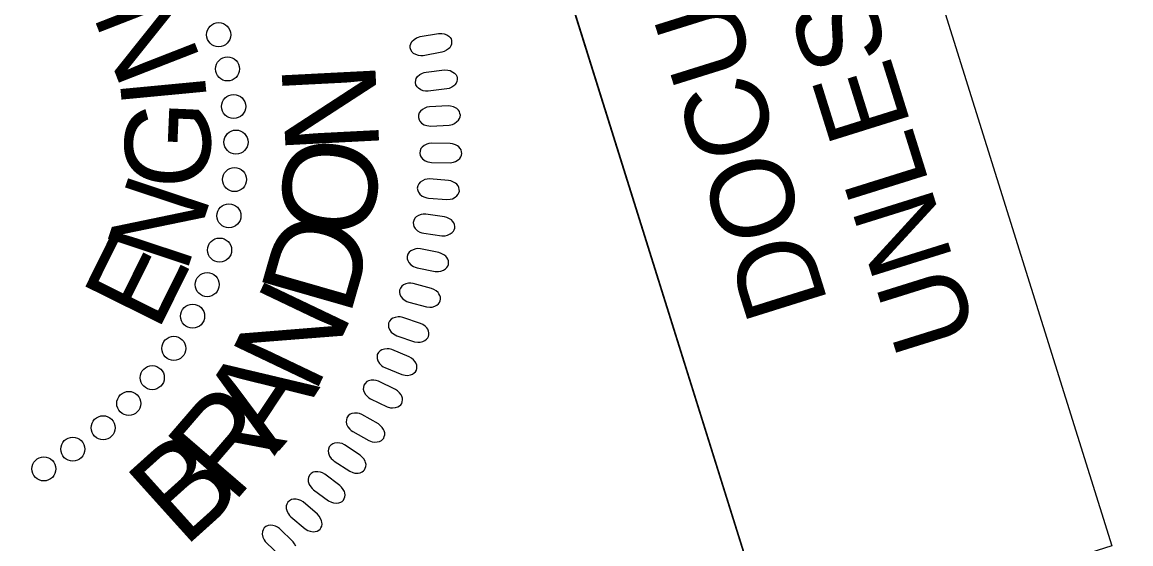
# Model space of a CAD drawing. Extents: x 473667 to 478950, y 494687 to 505998.
# Drawn here: x 473846.6 to 473920.4, y 505522 to 505556.7 of the extents above; entities that cross this region are included whole.
import ezdxf

# ---------------------------------------------------------------- set-up
doc = ezdxf.new("R2010")
doc.units = 0
for name, color, linetype in [('Sheet Layout Plan Border', 7, 'Continuous'), ('Sheet PE Seal Cell', 7, 'Continuous'), ('Sheet Plan CELL', 7, 'Continuous'), ('Sheet Sticker Exception Certification CELL', 7, 'Continuous')]:
    doc.layers.add(name, color=color, linetype=linetype)

msp = doc.modelspace()

# ---------------------------------------------------------------- linework, layer by layer
at = {"layer": 'Sheet Layout Plan Border'}
msp.add_lwpolyline([(474406.845, 504597.013), (474903.647, 504485.248), (475129.181, 504591.075), (474710.642, 505927.062), (474746.684, 505812.014), (474670.328, 505788.092), (474619.338, 505950.854), (473859.326, 505712.757), (473919.128, 505521.868), (473753.519, 505469.973), (474127.2, 504277.174)], close=True, dxfattribs=at)
at = {"layer": 'Sheet PE Seal Cell'}
for points in [[(473873.109, 505555.763), (473874.316, 505555.979), (473874.538, 505555.981), (473874.686, 505555.955), (473874.872, 505555.874), (473874.997, 505555.798), (473875.096, 505555.702), (473875.153, 505555.606), (473875.193, 505555.499), (473875.193, 505555.385), (473875.185, 505555.262), (473875.145, 505555.148), (473875.064, 505555.028), (473874.996, 505554.955), (473874.861, 505554.862), (473874.695, 505554.772), (473874.542, 505554.721), (473873.307, 505554.492), (473873.136, 505554.484), (473872.99, 505554.504), (473872.818, 505554.564), (473872.66, 505554.649), (473872.565, 505554.731), (473872.478, 505554.875), (473872.432, 505555.019), (473872.445, 505555.173), (473872.475, 505555.285), (473872.551, 505555.428), (473872.697, 505555.574), (473872.862, 505555.673), (473872.984, 505555.725)], [(473873.505, 505553.407), (473874.724, 505553.548), (473874.946, 505553.536), (473875.091, 505553.5), (473875.272, 505553.408), (473875.392, 505553.324), (473875.484, 505553.222), (473875.536, 505553.122), (473875.568, 505553.013), (473875.561, 505552.9), (473875.545, 505552.777), (473875.498, 505552.667), (473875.411, 505552.551), (473875.338, 505552.483), (473875.197, 505552.399), (473875.026, 505552.319), (473874.87, 505552.278), (473873.623, 505552.127), (473873.451, 505552.13), (473873.308, 505552.159), (473873.139, 505552.229), (473872.987, 505552.324), (473872.897, 505552.412), (473872.82, 505552.561), (473872.783, 505552.708), (473872.806, 505552.86), (473872.843, 505552.97), (473872.927, 505553.108), (473873.082, 505553.245), (473873.253, 505553.333), (473873.377, 505553.377)], [(473873.806, 505549.811), (473875.031, 505549.875), (473875.248, 505549.923), (473875.385, 505549.982), (473875.549, 505550.104), (473875.653, 505550.206), (473875.727, 505550.323), (473875.762, 505550.429), (473875.776, 505550.542), (473875.749, 505550.653), (473875.713, 505550.771), (473875.649, 505550.872), (473875.543, 505550.971), (473875.461, 505551.027), (473875.308, 505551.086), (473875.125, 505551.137), (473874.965, 505551.151), (473873.71, 505551.094), (473873.542, 505551.062), (473873.404, 505551.01), (473873.25, 505550.912), (473873.116, 505550.793), (473873.042, 505550.692), (473872.99, 505550.531), (473872.978, 505550.382), (473873.025, 505550.234), (473873.081, 505550.132), (473873.187, 505550.01), (473873.362, 505549.9), (473873.545, 505549.842), (473873.676, 505549.819)], [(473873.861, 505547.384), (473875.088, 505547.37), (473875.308, 505547.405), (473875.448, 505547.456), (473875.619, 505547.566), (473875.73, 505547.662), (473875.811, 505547.774), (473875.851, 505547.877), (473875.873, 505547.99), (473875.854, 505548.102), (473875.825, 505548.222), (473875.767, 505548.327), (473875.668, 505548.433), (473875.589, 505548.494), (473875.44, 505548.562), (473875.261, 505548.624), (473875.102, 505548.649), (473873.846, 505548.67), (473873.675, 505548.649), (473873.536, 505548.605), (473873.375, 505548.517), (473873.234, 505548.407), (473873.153, 505548.31), (473873.092, 505548.155), (473873.07, 505548.005), (473873.109, 505547.855), (473873.158, 505547.75), (473873.255, 505547.622), (473873.424, 505547.501), (473873.603, 505547.431), (473873.732, 505547.4)], [(473873.661, 505545.006), (473874.884, 505544.916), (473875.106, 505544.937), (473875.249, 505544.978), (473875.427, 505545.078), (473875.543, 505545.167), (473875.631, 505545.273), (473875.678, 505545.374), (473875.707, 505545.485), (473875.695, 505545.598), (473875.674, 505545.72), (473875.622, 505545.828), (473875.53, 505545.94), (473875.455, 505546.005), (473875.311, 505546.083), (473875.136, 505546.156), (473874.979, 505546.191), (473873.726, 505546.291), (473873.555, 505546.281), (473873.413, 505546.246), (473873.247, 505546.169), (473873.099, 505546.067), (473873.013, 505545.976), (473872.941, 505545.824), (473872.91, 505545.676), (473872.94, 505545.524), (473872.982, 505545.416), (473873.071, 505545.282), (473873.232, 505545.15), (473873.406, 505545.07), (473873.533, 505545.031)], [(473873.335, 505542.675), (473874.55, 505542.508), (473874.772, 505542.515), (473874.918, 505542.547), (473875.101, 505542.636), (473875.223, 505542.717), (473875.317, 505542.817), (473875.371, 505542.915), (473875.406, 505543.024), (473875.401, 505543.137), (473875.388, 505543.26), (473875.343, 505543.372), (473875.258, 505543.489), (473875.188, 505543.56), (473875.049, 505543.646), (473874.879, 505543.73), (473874.724, 505543.774), (473873.48, 505543.953), (473873.309, 505543.953), (473873.165, 505543.927), (473872.994, 505543.861), (473872.841, 505543.769), (473872.748, 505543.683), (473872.668, 505543.536), (473872.628, 505543.39), (473872.647, 505543.237), (473872.682, 505543.126), (473872.763, 505542.987), (473872.915, 505542.846), (473873.084, 505542.754), (473873.208, 505542.707)], [(473872.895, 505540.378), (473874.097, 505540.136), (473874.319, 505540.129), (473874.467, 505540.152), (473874.655, 505540.229), (473874.782, 505540.302), (473874.882, 505540.396), (473874.942, 505540.491), (473874.984, 505540.597), (473874.986, 505540.71), (473874.981, 505540.834), (473874.943, 505540.948), (473874.866, 505541.07), (473874.8, 505541.145), (473874.666, 505541.241), (473874.502, 505541.335), (473874.35, 505541.389), (473873.12, 505541.644), (473872.95, 505541.656), (473872.803, 505541.639), (473872.629, 505541.583), (473872.47, 505541.502), (473872.373, 505541.422), (473872.283, 505541.28), (473872.234, 505541.137), (473872.244, 505540.983), (473872.272, 505540.87), (473872.344, 505540.726), (473872.487, 505540.576), (473872.649, 505540.473), (473872.77, 505540.419)], [(473872.338, 505538.09), (473873.523, 505537.772), (473873.744, 505537.751), (473873.893, 505537.765), (473874.086, 505537.829), (473874.216, 505537.895), (473874.322, 505537.982), (473874.389, 505538.073), (473874.436, 505538.176), (473874.447, 505538.289), (473874.449, 505538.413), (473874.418, 505538.529), (473874.349, 505538.656), (473874.287, 505538.735), (473874.161, 505538.839), (473874.003, 505538.943), (473873.854, 505539.006), (473872.643, 505539.339), (473872.473, 505539.361), (473872.327, 505539.354), (473872.149, 505539.309), (473871.985, 505539.237), (473871.883, 505539.163), (473871.784, 505539.028), (473871.727, 505538.888), (473871.727, 505538.733), (473871.747, 505538.619), (473871.81, 505538.471), (473871.943, 505538.312), (473872.1, 505538.2), (473872.217, 505538.137)], [(473871.558, 505535.852), (473872.721, 505535.461), (473872.94, 505535.426), (473873.089, 505535.431), (473873.286, 505535.483), (473873.421, 505535.54), (473873.532, 505535.621), (473873.604, 505535.707), (473873.658, 505535.807), (473873.675, 505535.92), (473873.685, 505536.043), (473873.662, 505536.161), (473873.6, 505536.292), (473873.545, 505536.374), (473873.423, 505536.486), (473873.273, 505536.6), (473873.129, 505536.672), (473871.941, 505537.08), (473871.773, 505537.113), (473871.626, 505537.115), (473871.446, 505537.081), (473871.278, 505537.02), (473871.172, 505536.953), (473871.064, 505536.824), (473870.997, 505536.688), (473870.988, 505536.533), (473871.002, 505536.418), (473871.055, 505536.266), (473871.178, 505536.099), (473871.327, 505535.978), (473871.44, 505535.908)], [(473870.754, 505533.734), (473871.89, 505533.27), (473872.107, 505533.222), (473872.256, 505533.217), (473872.455, 505533.257), (473872.594, 505533.306), (473872.71, 505533.379), (473872.787, 505533.461), (473872.848, 505533.557), (473872.871, 505533.668), (473872.888, 505533.79), (473872.873, 505533.909), (473872.819, 505534.045), (473872.769, 505534.13), (473872.656, 505534.249), (473872.513, 505534.372), (473872.373, 505534.453), (473871.212, 505534.935), (473871.047, 505534.979), (473870.9, 505534.989), (473870.719, 505534.967), (473870.548, 505534.917), (473870.436, 505534.857), (473870.322, 505534.734), (473870.247, 505534.603), (473870.228, 505534.45), (473870.235, 505534.333), (473870.279, 505534.178), (473870.39, 505534.004), (473870.531, 505533.873), (473870.64, 505533.797)], [(473869.799, 505531.664), (473870.903, 505531.13), (473871.117, 505531.068), (473871.265, 505531.054), (473871.467, 505531.081), (473871.609, 505531.121), (473871.729, 505531.187), (473871.81, 505531.263), (473871.877, 505531.356), (473871.907, 505531.465), (473871.932, 505531.586), (473871.925, 505531.706), (473871.88, 505531.844), (473871.835, 505531.932), (473871.729, 505532.059), (473871.594, 505532.19), (473871.46, 505532.28), (473870.332, 505532.834), (473870.17, 505532.888), (473870.024, 505532.908), (473869.842, 505532.897), (473869.668, 505532.857), (473869.553, 505532.804), (473869.431, 505532.689), (473869.347, 505532.563), (473869.319, 505532.411), (473869.318, 505532.295), (473869.352, 505532.137), (473869.453, 505531.956), (473869.585, 505531.817), (473869.689, 505531.734)], [(473868.621, 505529.476), (473869.689, 505528.874), (473869.898, 505528.798), (473870.046, 505528.775), (473870.249, 505528.789), (473870.392, 505528.82), (473870.517, 505528.879), (473870.603, 505528.951), (473870.675, 505529.038), (473870.713, 505529.146), (473870.745, 505529.265), (473870.745, 505529.385), (473870.709, 505529.525), (473870.669, 505529.616), (473870.572, 505529.749), (473870.445, 505529.889), (473870.317, 505529.987), (473869.226, 505530.611), (473869.067, 505530.675), (473868.924, 505530.704), (473868.741, 505530.705), (473868.564, 505530.676), (473868.447, 505530.63), (473868.317, 505530.523), (473868.227, 505530.402), (473868.188, 505530.252), (473868.18, 505530.136), (473868.205, 505529.977), (473868.293, 505529.79), (473868.417, 505529.642), (473868.515, 505529.553)], [(473867.383, 505527.506), (473868.411, 505526.837), (473868.615, 505526.749), (473868.761, 505526.717), (473868.964, 505526.718), (473869.109, 505526.74), (473869.237, 505526.791), (473869.327, 505526.856), (473869.405, 505526.94), (473869.449, 505527.045), (473869.49, 505527.161), (473869.497, 505527.281), (473869.47, 505527.423), (473869.436, 505527.517), (473869.347, 505527.656), (473869.229, 505527.803), (473869.108, 505527.909), (473868.058, 505528.6), (473867.904, 505528.674), (473867.762, 505528.712), (473867.58, 505528.724), (473867.401, 505528.706), (473867.281, 505528.668), (473867.146, 505528.569), (473867.048, 505528.454), (473867, 505528.308), (473866.985, 505528.193), (473866.999, 505528.031), (473867.075, 505527.839), (473867.189, 505527.684), (473867.282, 505527.589)], [(473866.006, 505525.604), (473866.992, 505524.872), (473867.19, 505524.772), (473867.333, 505524.729), (473867.536, 505524.719), (473867.682, 505524.732), (473867.813, 505524.774), (473867.907, 505524.834), (473867.991, 505524.912), (473868.041, 505525.014), (473868.088, 505525.128), (473868.103, 505525.248), (473868.085, 505525.391), (473868.057, 505525.487), (473867.977, 505525.63), (473867.869, 505525.785), (473867.754, 505525.898), (473866.75, 505526.654), (473866.6, 505526.737), (473866.461, 505526.784), (473866.28, 505526.807), (473866.102, 505526.801), (473865.979, 505526.771), (473865.837, 505526.68), (473865.732, 505526.572), (473865.675, 505526.428), (473865.653, 505526.314), (473865.656, 505526.153), (473865.722, 505525.956), (473865.826, 505525.794), (473865.912, 505525.693)], [(473864.503, 505523.796), (473865.441, 505523.003), (473865.632, 505522.89), (473865.772, 505522.84), (473865.975, 505522.816), (473866.121, 505522.819), (473866.254, 505522.853), (473866.352, 505522.908), (473866.44, 505522.981), (473866.497, 505523.079), (473866.551, 505523.19), (473866.573, 505523.308), (473866.565, 505523.452), (473866.542, 505523.549), (473866.472, 505523.698), (473866.373, 505523.859), (473866.266, 505523.979), (473865.311, 505524.797), (473865.168, 505524.889), (473865.031, 505524.945), (473864.852, 505524.979), (473864.673, 505524.984), (473864.549, 505524.961), (473864.402, 505524.88), (473864.29, 505524.779), (473864.224, 505524.639), (473864.195, 505524.527), (473864.189, 505524.365), (473864.241, 505524.165), (473864.335, 505523.997), (473864.415, 505523.891)]]:
    msp.add_lwpolyline(points, close=True, dxfattribs=at)
msp.add_lwpolyline([(473864.827, 505521.851), (473864.739, 505522.018), (473864.64, 505522.145), (473863.738, 505523.02), (473863.6, 505523.122), (473863.468, 505523.185), (473863.291, 505523.231), (473863.113, 505523.247), (473862.988, 505523.233), (473862.836, 505523.16), (473862.718, 505523.066), (473862.644, 505522.931), (473862.607, 505522.821), (473862.591, 505522.66), (473862.631, 505522.457), (473862.714, 505522.283), (473862.786, 505522.172), (473862.87, 505522.072), (473863.755, 505521.222)], dxfattribs=at)
for centre in [(473859.694, 505555.891), (473860.282, 505553.613), (473860.689, 505551.112), (473860.846, 505548.742), (473860.749, 505546.25), (473860.376, 505543.839), (473859.754, 505541.559), (473858.93, 505539.257), (473857.959, 505537.159), (473856.709, 505535.016), (473855.274, 505533.065), (473853.712, 505531.351), (473852.006, 505529.732), (473849.988, 505528.308), (473848.062, 505526.996)]:
    msp.add_circle(centre, 0.801, dxfattribs=at)
at = {"layer": 'Sheet Plan CELL'}
for points in [[(475144.128, 504543.362), (474142.179, 504229.444), (473753.507, 505469.969), (473896.703, 505514.843), (473836.913, 505705.736), (474695.694, 505974.775)], [(473789.364, 505481.202), (473759.453, 505576.677), (473866.82, 505610.313), (473896.703, 505514.843)]]:
    msp.add_lwpolyline(points, close=True, dxfattribs=at)
at = {"layer": 'Sheet Sticker Exception Certification CELL'}
for p, q in [((473859.326, 505712.757), (473919.128, 505521.868)), ((473859.326, 505712.757), (473919.128, 505521.868)), ((473896.703, 505514.843), (473836.901, 505705.732)), ((473896.703, 505514.843), (473836.901, 505705.732))]:
    msp.add_line(p, q, dxfattribs=at)

# ---------------------------------------------------------------- texts
at = {"layer": 'Sheet PE Seal Cell'}
for s, height, rotation, p in [('N', 5.669, 111.29913, (473858.563, 505554.179)), ('N', 6.236, 92.94526, (473870.397, 505548.171)), ('I', 5.669, 95.41953, (473858.935, 505551.41)), ('G', 5.669, 87.47974, (473859.006, 505545.534)), ('O', 6.236, 82.84542, (473869.793, 505542.164)), ('N', 5.669, 71.60014, (473857.512, 505539.937)), ('D', 6.236, 73.97719, (473868.401, 505537.048)), ('E', 5.669, 63.66034, (473855.629, 505536.062)), ('N', 6.236, 64.4875, (473866.057, 505531.881)), ('A', 6.236, 56.37633, (473863.401, 505527.822)), ('R', 6.236, 49.25949, (473860.619, 505524.6)), ('B', 6.236, 41.98446, (473857.385, 505521.689))]:
    msp.add_text(s, height=height, rotation=rotation, dxfattribs=at).set_placement(p)
at = {"layer": 'Sheet Sticker Exception Certification CELL'}
for s, p in [('UNLESS ALL SIGNATURES COMPLETED', (473910.19, 505535.834)), ('UNLESS ALL SIGNATURES COMPLETED', (473910.19, 505535.834)), ('DOCUMENT NOT CONSIDERED FINAL', (473900.276, 505538.043)), ('DOCUMENT NOT CONSIDERED FINAL', (473900.276, 505538.043))]:
    msp.add_text(s, height=5.5, rotation=107.39476, dxfattribs=at).set_placement(p)

doc.saveas('drawing.dxf')
